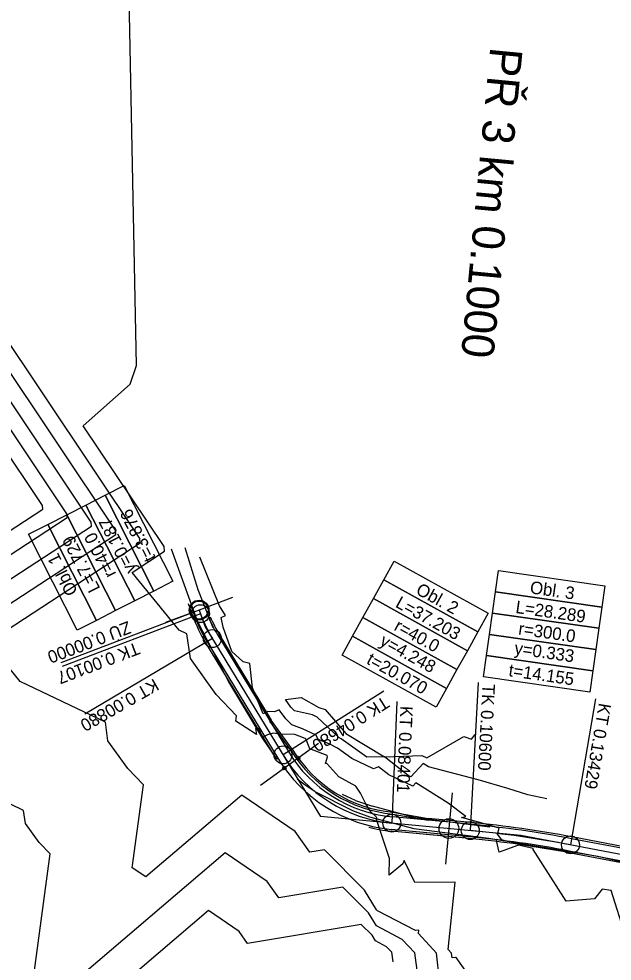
# Model space of a CAD drawing. Extents: x -549394 to -546608, y -1037055 to -1033629.
# Drawn here: x -547175.8 to -547010.1, y -1035814.9 to -1035551.8 of the extents above; entities that cross this region are included whole.
import ezdxf

# ---------------------------------------------------------------- set-up
doc = ezdxf.new("R2010")
doc.units = 0
for name, color, linetype in [('hlavni_vrst', 7, 'Continuous'), ('hrana_L', 7, 'Continuous'), ('norm_vrst', 7, 'Continuous'), ('POLYGONY_SITUACE_PO', 7, 'Continuous'), ('u_sirka_0_5m', 7, 'Continuous'), ('x_navrh_C3', 7, 'Continuous'), ('x_osa_C3', 7, 'Continuous'), ('x_popis_oblouky_C3', 7, 'Continuous'), ('x_popis_pricne_rezy_C3', 7, 'Continuous')]:
    doc.layers.add(name, color=color, linetype=linetype)

msp = doc.modelspace()

# ---------------------------------------------------------------- linework, layer by layer
at = {"layer": 'hlavni_vrst'}
for p, q in [((-547162.43, -1035690), (-547254.53, -1035552.4)), ((-547270.81, -1035761.75), (-547162.32, -1035691.07)), ((-547162.32, -1035691.07), (-547162.43, -1035690)), ((-547119.76, -1035715.7), (-547125.23, -1035702.15)), ((-547118.11, -1035718.38), (-547119.76, -1035715.7)), ((-547119.32, -1035718.91), (-547118.11, -1035718.38)), ((-547118.72, -1035721.68), (-547119.32, -1035718.91)), ((-547116.35, -1035728.46), (-547118.72, -1035721.68)), ((-547113.14, -1035731.35), (-547116.35, -1035728.46)), ((-547111.32, -1035731.79), (-547113.14, -1035731.35)), ((-547110.54, -1035738.54), (-547111.32, -1035731.79)), ((-547107.57, -1035745.83), (-547110.54, -1035738.54)), ((-547106.28, -1035745.18), (-547107.57, -1035745.83)), ((-547104.38, -1035745.28), (-547106.28, -1035745.18)), ((-547103.1, -1035744.71), (-547104.38, -1035745.28)), ((-547101.24, -1035747.24), (-547103.1, -1035744.71)), ((-547099.56, -1035748.9), (-547101.24, -1035747.24)), ((-547096.55, -1035750.05), (-547099.56, -1035748.9)), ((-547092.78, -1035751.76), (-547096.55, -1035750.05)), ((-547092.25, -1035752.99), (-547092.78, -1035751.76)), ((-547089.09, -1035754.2), (-547092.25, -1035752.99)), ((-547086.83, -1035755.45), (-547089.09, -1035754.2)), ((-547082.83, -1035758.29), (-547086.83, -1035755.45)), ((-547076.73, -1035761.22), (-547082.83, -1035758.29)), ((-547075.38, -1035760.61), (-547076.73, -1035761.22)), ((-547072.5, -1035762.9), (-547075.38, -1035760.61)), ((-547065.74, -1035766.01), (-547072.5, -1035762.9)), ((-547064.9, -1035765.1), (-547065.74, -1035766.01)), ((-547055.9, -1035770.76), (-547064.9, -1035765.1)), ((-547050.97, -1035774.54), (-547055.9, -1035770.76)), ((-547052.14, -1035774.74), (-547050.97, -1035774.54)), ((-547044.71, -1035776.82), (-547052.14, -1035774.74)), ((-547041.66, -1035777.75), (-547044.71, -1035776.82)), ((-547042.1, -1035779.39), (-547041.66, -1035777.75)), ((-547041.65, -1035784.48), (-547042.49, -1035780.85)), ((-547042.49, -1035780.85), (-547039.99, -1035781.26)), ((-547040.91, -1035781.03), (-547042.1, -1035779.39)), ((-547039.99, -1035781.26), (-547040.91, -1035781.03)), ((-547036.28, -1035782.48), (-547041.65, -1035784.48)), ((-547032.12, -1035783.41), (-547036.28, -1035782.48)), ((-547032.16, -1035783.69), (-547032.12, -1035783.41)), ((-547022.93, -1035798.11), (-547032.16, -1035783.69)), ((-547012.88, -1035794.76), (-547015.05, -1035797.51)), ((-547010.39, -1035795.15), (-547012.88, -1035794.76)), ((-547006.35, -1035807.78), (-547010.39, -1035795.15)), ((-547015.05, -1035797.51), (-547022.93, -1035798.11))]:
    msp.add_line(p, q, dxfattribs=at)
at = {"layer": 'hrana_L'}
for p, q in [((-547133.31, -1035699.8), (-547126.03, -1035719.9)), ((-547125.75, -1035711.25), (-547129.4, -1035699.51)), ((-547121.54, -1035721.79), (-547125.75, -1035711.25)), ((-547126.03, -1035719.9), (-547116.97, -1035737.34)), ((-547116.97, -1035737.34), (-547107.79, -1035752.71)), ((-547107.79, -1035752.71), (-547104.47, -1035757.48)), ((-547104.47, -1035757.48), (-547103.62, -1035758.54)), ((-547095.87, -1035765.77), (-547098.09, -1035764.1)), ((-547093.16, -1035767.56), (-547095.87, -1035765.77)), ((-547093.16, -1035767.56), (-547082.65, -1035772.78)), ((-547081.81, -1035770.01), (-547085.39, -1035768.38)), ((-547081.81, -1035770.01), (-547076.99, -1035771.58)), ((-547082.65, -1035772.78), (-547077.83, -1035774.58)), ((-547065.04, -1035774.86), (-547076.99, -1035771.58)), ((-547077.83, -1035774.58), (-547065.49, -1035777.83)), ((-547044.23, -1035777.49), (-547065.04, -1035774.86)), ((-547065.49, -1035777.83), (-547044.51, -1035780.5)), ((-547044.51, -1035780.5), (-547014.03, -1035785.6)), ((-547014.03, -1035785.6), (-546993.98, -1035790.12))]:
    msp.add_line(p, q, dxfattribs=at)
at = {"layer": 'norm_vrst'}
for p, q in [((-547142.94, -1035648.57), (-547145.95, -1035499.25)), ((-547148.85, -1035694.57), (-547251.98, -1035540.5)), ((-547155.64, -1035692.29), (-547253.25, -1035546.45)), ((-547142.07, -1035696.85), (-547242.38, -1035546.99)), ((-547169.21, -1035687.72), (-547255.8, -1035558.35)), ((-547144.77, -1035653.79), (-547142.94, -1035648.57)), ((-547157.83, -1035665.45), (-547144.77, -1035653.79)), ((-547135.28, -1035699.14), (-547157.83, -1035665.45)), ((-547271.11, -1035755.18), (-547169.11, -1035688.72)), ((-547169.11, -1035688.72), (-547169.21, -1035687.72)), ((-547264.92, -1035764.69), (-547155.53, -1035693.41)), ((-547155.53, -1035693.41), (-547155.64, -1035692.29)), ((-547148.73, -1035695.76), (-547148.85, -1035694.57)), ((-547224.67, -1035745.24), (-547148.73, -1035695.76)), ((-547141.94, -1035698.11), (-547142.07, -1035696.85)), ((-547184.42, -1035725.79), (-547141.94, -1035698.11)), ((-547135.14, -1035700.46), (-547135.28, -1035699.14)), ((-547144.18, -1035706.34), (-547135.14, -1035700.46)), ((-547131.02, -1035722.49), (-547144.18, -1035706.34)), ((-547128.86, -1035723.52), (-547131.02, -1035722.49)), ((-547127.92, -1035730.37), (-547128.86, -1035723.52)), ((-547175.46, -1035736.8), (-547184.42, -1035725.79)), ((-547120.68, -1035740.44), (-547127.92, -1035730.37)), ((-547151.67, -1035748.16), (-547175.46, -1035736.8)), ((-547114.98, -1035746.4), (-547120.68, -1035740.44)), ((-547101.36, -1035741.88), (-547096.97, -1035741.25)), ((-547099.84, -1035743.95), (-547101.36, -1035741.88)), ((-547096.97, -1035741.25), (-547092.03, -1035744.04)), ((-547098.79, -1035744.99), (-547099.84, -1035743.95)), ((-547092.03, -1035744.04), (-547090.21, -1035744.59)), ((-547090.21, -1035744.59), (-547084.45, -1035751.36)), ((-547115.18, -1035747.91), (-547114.98, -1035746.4)), ((-547093.75, -1035746.09), (-547098.79, -1035744.99)), ((-547092.47, -1035746.77), (-547093.75, -1035746.09)), ((-547086.48, -1035752.45), (-547092.47, -1035746.77)), ((-547150.95, -1035753.4), (-547151.67, -1035748.16)), ((-547109.47, -1035751.65), (-547115.18, -1035747.91)), ((-547109.72, -1035749.47), (-547109.33, -1035750.16)), ((-547108.72, -1035750.14), (-547109.72, -1035749.47)), ((-547174.49, -1035772.8), (-547219.89, -1035751.1)), ((-547109.33, -1035750.16), (-547109.74, -1035749.92)), ((-547109.74, -1035749.92), (-547109.47, -1035751.65)), ((-547107.78, -1035752.45), (-547108.72, -1035750.14)), ((-547106.32, -1035751.7), (-547107.78, -1035752.45)), ((-547104.82, -1035751.21), (-547106.32, -1035751.7)), ((-547102.85, -1035751.5), (-547104.82, -1035751.21)), ((-547098.7, -1035751.63), (-547102.85, -1035751.5)), ((-547096.32, -1035752.55), (-547098.7, -1035751.63)), ((-547085.76, -1035752.84), (-547086.48, -1035752.45)), ((-547084.45, -1035751.36), (-547073.72, -1035757.81)), ((-547061.85, -1035758.15), (-547051.54, -1035752.15)), ((-547051.54, -1035752.15), (-547049.41, -1035752.95)), ((-547049.41, -1035752.95), (-547048.34, -1035751.56)), ((-547145.41, -1035761.11), (-547150.95, -1035753.4)), ((-547095.69, -1035752.83), (-547096.32, -1035752.55)), ((-547094.49, -1035755.63), (-547095.69, -1035752.83)), ((-547078.6, -1035757.93), (-547085.76, -1035752.84)), ((-547089.7, -1035757.46), (-547094.49, -1035755.63)), ((-547089.6, -1035757.81), (-547089.7, -1035757.46)), ((-547073.72, -1035757.81), (-547063.29, -1035757.51)), ((-547063.29, -1035757.51), (-547061.85, -1035758.15)), ((-547090.19, -1035759.74), (-547089.6, -1035757.81)), ((-547089.83, -1035759.74), (-547090.19, -1035759.74)), ((-547086.44, -1035763.39), (-547089.83, -1035759.74)), ((-547073.72, -1035757.81), (-547078.6, -1035757.93)), ((-547073.72, -1035757.81), (-547073.72, -1035757.81)), ((-547073.72, -1035757.81), (-547073.72, -1035757.81)), ((-547073.72, -1035757.81), (-547073.72, -1035757.81)), ((-547067.1, -1035763.08), (-547073.72, -1035757.81)), ((-547062.85, -1035759.69), (-547066.32, -1035763.43)), ((-547061.39, -1035760.61), (-547062.85, -1035759.69)), ((-547141.05, -1035765.67), (-547145.41, -1035761.11)), ((-547047.55, -1035764.26), (-547061.39, -1035760.61)), ((-547144.14, -1035788.82), (-547141.05, -1035765.67)), ((-547081.68, -1035765.99), (-547086.44, -1035763.39)), ((-547066.32, -1035763.43), (-547067.1, -1035763.08)), ((-547039.2, -1035766.69), (-547047.55, -1035764.26)), ((-547080.36, -1035767.97), (-547081.68, -1035765.99)), ((-547078.92, -1035770.95), (-547080.36, -1035767.97)), ((-547033.59, -1035768.43), (-547039.2, -1035766.69)), ((-547113.56, -1035768.54), (-547140.31, -1035791.32)), ((-547098.64, -1035778.68), (-547113.56, -1035768.54)), ((-547078.3, -1035771.86), (-547078.92, -1035770.95)), ((-547028.36, -1035769.53), (-547033.59, -1035768.43)), ((-547173.98, -1035776.43), (-547174.49, -1035772.8)), ((-547077.45, -1035773.22), (-547078.3, -1035771.86)), ((-547076, -1035774.62), (-547077.45, -1035773.22)), ((-547076.04, -1035775.07), (-547075.7, -1035775.14)), ((-547072.24, -1035786.23), (-547076.04, -1035775.07)), ((-547075.7, -1035775.14), (-547076, -1035774.62)), ((-547170.14, -1035781.78), (-547173.98, -1035776.43)), ((-547094.5, -1035784.45), (-547098.64, -1035778.68)), ((-547167.12, -1035784.94), (-547170.14, -1035781.78)), ((-547090.47, -1035783.78), (-547094.5, -1035784.45)), ((-547079.24, -1035795.04), (-547090.47, -1035783.78)), ((-547173.1, -1035829.73), (-547167.12, -1035784.94)), ((-547118.23, -1035784.65), (-547172, -1035830.44)), ((-547106.48, -1035792.64), (-547118.23, -1035784.65)), ((-547072.34, -1035790.87), (-547072.24, -1035786.23)), ((-547140.31, -1035791.32), (-547144.14, -1035788.82)), ((-547068.52, -1035787.69), (-547072.34, -1035790.87)), ((-547068.17, -1035786.78), (-547068.52, -1035787.69)), ((-547065.22, -1035792.95), (-547068.17, -1035786.78)), ((-547103.21, -1035797.19), (-547106.48, -1035792.64)), ((-547085.31, -1035794.19), (-547103.21, -1035797.19)), ((-547078.18, -1035801.34), (-547085.31, -1035794.19)), ((-547053.89, -1035792.84), (-547065.22, -1035792.95)), ((-547055.88, -1035811.62), (-547053.89, -1035792.84)), ((-547075.91, -1035800.52), (-547079.24, -1035795.04)), ((-547122.89, -1035800.77), (-547175.77, -1035845.79)), ((-547114.31, -1035806.6), (-547122.89, -1035800.77)), ((-547075.93, -1035805.04), (-547078.18, -1035801.34)), ((-547075.67, -1035800.82), (-547075.91, -1035800.52)), ((-547075.64, -1035800.85), (-547075.67, -1035800.82)), ((-547065, -1035806.27), (-547075.64, -1035800.85)), ((-547080.15, -1035804.6), (-547111.93, -1035809.92)), ((-547077.12, -1035807.65), (-547080.15, -1035804.6)), ((-547068.74, -1035808.83), (-547075.93, -1035805.04)), ((-547111.93, -1035809.92), (-547114.31, -1035806.6)), ((-547076.16, -1035809.22), (-547077.12, -1035807.65)), ((-547064.08, -1035806.26), (-547065, -1035806.27)), ((-547064.18, -1035807.15), (-547064.08, -1035806.26)), ((-547059.16, -1035812.61), (-547064.18, -1035807.15)), ((-547073.1, -1035810.83), (-547076.16, -1035809.22)), ((-547065.22, -1035812.51), (-547068.74, -1035808.83)), ((-547071.6, -1035812.4), (-547073.1, -1035810.83)), ((-547071.22, -1035815.06), (-547071.6, -1035812.4)), ((-547064.32, -1035818.79), (-547065.22, -1035812.51)), ((-547058.28, -1035820.05), (-547059.16, -1035812.61)), ((-547054.97, -1035812.6), (-547055.88, -1035811.62)), ((-547054.81, -1035813.94), (-547054.97, -1035812.6)), ((-547053.86, -1035813.86), (-547054.81, -1035813.94)), ((-547053.67, -1035813.88), (-547053.86, -1035813.86)), ((-547049.05, -1035820.28), (-547053.67, -1035813.88))]:
    msp.add_line(p, q, dxfattribs=at)
at = {"layer": 'POLYGONY_SITUACE_PO'}
for centre in [(-547125.48, -1035716.87), (-547125.11, -1035717.88), (-547121.76, -1035724.83), (-547102.02, -1035757.3), (-547071.61, -1035776.34), (-547049.71, -1035778.42), (-547021.72, -1035782.42)]:
    msp.add_circle(centre, 2.5, dxfattribs=at)
at = {"layer": 'u_sirka_0_5m'}
for centre, radius in [((-547125.48, -1035716.87), 2.75), ((-547097.79, -1035758.18), 0.5), ((-547101.67, -1035760.99), 0.5), ((-547055.69, -1035777.85), 2.75)]:
    msp.add_circle(centre, radius, dxfattribs=at)
at = {"layer": 'x_navrh_C3'}
for p, q in [((-547127.87, -1035715.43), (-547126.75, -1035718.48)), ((-547123.25, -1035725.73), (-547103.51, -1035758.21)), ((-547120.26, -1035723.92), (-547100.52, -1035756.39)), ((-547099.85, -1035755.98), (-547105.72, -1035747.85)), ((-547099.43, -1035755.7), (-547105.3, -1035747.57)), ((-547071.31, -1035773.32), (-547061.43, -1035775.05)), ((-547049.55, -1035776.68), (-547071.45, -1035774.6)), ((-547071.37, -1035773.82), (-547061.49, -1035775.55)), ((-547049.93, -1035780.66), (-547071.83, -1035778.58)), ((-547049.88, -1035780.16), (-547071.78, -1035778.09)), ((-546982.7, -1035788.09), (-547021.39, -1035780.7)), ((-546983.36, -1035791.53), (-547022.05, -1035784.13))]:
    msp.add_line(p, q, dxfattribs=at)
for points in [[(-547128.56, -1035715.02), (-547127.22, -1035718.65)], [(-547123.68, -1035725.99), (-547103.94, -1035758.47)], [(-547119.83, -1035723.66), (-547105.3, -1035747.57)], [(-547049.5, -1035776.18), (-547061.43, -1035775.05)], [(-547049.93, -1035780.66), (-547062.08, -1035779.51)], [(-546982.61, -1035787.6), (-547021.3, -1035780.21)], [(-546983.45, -1035792.02), (-547022.14, -1035784.63)]]:
    msp.add_lwpolyline(points, dxfattribs=at)
for centre, radius, start, end in [((-547087.57, -1035704.05), 38.25, 201.9092, 211.2924), ((-547087.57, -1035704.05), 42.25, 200.2219, 211.2924), ((-547087.57, -1035704.05), 41.75, 200.2219, 211.2924), ((-547087.57, -1035704.05), 37.75, 202.9245, 211.2924), ((-547067.84, -1035736.52), 38.25, 211.2924, 264.5817), ((-547067.84, -1035736.52), 37.46, 211.2924, 264.5817), ((-547067.84, -1035736.52), 36.96, 211.262, 264.6122), ((-547067.84, -1035736.52), 41.75, 211.2924, 264.5817), ((-547078.04, -1036077.08), 302.25, 79.1789, 84.5817), ((-547067.84, -1035736.52), 42.25, 255.9517, 264.5817), ((-547078.04, -1036077.08), 301.75, 79.1789, 84.5817), ((-547078.04, -1036077.08), 297.75, 79.1789, 84.5817), ((-547078.04, -1036077.08), 298.25, 79.1789, 84.5817)]:
    msp.add_arc(centre, radius, start, end, dxfattribs=at)
at = {"layer": 'x_osa_C3'}
for points in [[(-547125.48, -1035716.87), (-547123.77, -1035721.51), (-547091.59, -1035774.45)], [(-546884.98, -1035809.13), (-546939.06, -1035799.39), (-546975.39, -1035791.27), (-547035.62, -1035779.76), (-547091.59, -1035774.45)]]:
    msp.add_lwpolyline(points, dxfattribs=at)
for centre, radius, start, end in [((-547087.57, -1035704.05), 40, 200.2219, 211.2924), ((-547067.84, -1035736.52), 40, 211.2924, 264.5817), ((-547078.04, -1036077.08), 300, 79.1789, 84.5817)]:
    msp.add_arc(centre, radius, start, end, dxfattribs=at)
at = {"layer": 'x_popis_oblouky_C3'}
for points in [[(-547138.12, -1035711.57), (-547151.74, -1035684.84), (-547146.39, -1035682.11), (-547132.77, -1035708.84)], [(-547143.46, -1035714.29), (-547157.08, -1035687.56), (-547151.74, -1035684.84), (-547138.12, -1035711.57)], [(-547148.81, -1035717.01), (-547162.43, -1035690.28), (-547157.08, -1035687.56), (-547143.46, -1035714.29)], [(-547154.16, -1035719.74), (-547167.77, -1035693.01), (-547162.43, -1035690.28), (-547148.81, -1035717.01)], [(-547159.5, -1035722.46), (-547173.12, -1035695.73), (-547167.77, -1035693.01), (-547154.16, -1035719.74)], [(-547070.97, -1035703.19), (-547044.72, -1035717.72), (-547047.63, -1035722.97), (-547073.87, -1035708.44)], [(-547041.79, -1035705.84), (-547012.09, -1035710.09), (-547012.94, -1035716.03), (-547042.64, -1035711.78)], [(-547073.87, -1035708.44), (-547047.63, -1035722.97), (-547050.53, -1035728.22), (-547076.78, -1035713.69)], [(-547042.64, -1035711.78), (-547012.94, -1035716.03), (-547013.79, -1035721.97), (-547043.49, -1035717.72)], [(-547076.78, -1035713.69), (-547050.53, -1035728.22), (-547053.44, -1035733.47), (-547079.69, -1035718.94)], [(-547043.49, -1035717.72), (-547013.79, -1035721.97), (-547014.64, -1035727.9), (-547044.33, -1035723.66)], [(-547079.69, -1035718.94), (-547053.44, -1035733.47), (-547056.34, -1035738.72), (-547082.59, -1035724.19)], [(-547082.59, -1035724.19), (-547056.34, -1035738.72), (-547059.25, -1035743.97), (-547085.5, -1035729.44)], [(-547044.33, -1035723.66), (-547014.64, -1035727.9), (-547015.48, -1035733.84), (-547045.18, -1035729.6)], [(-547045.18, -1035729.6), (-547015.48, -1035733.84), (-547016.33, -1035739.78), (-547046.03, -1035735.54)]]:
    msp.add_lwpolyline(points, close=True, dxfattribs=at)
for points in [[(-547125.48, -1035716.87), (-547164.13, -1035731.63)], [(-547125.11, -1035717.88), (-547163.76, -1035732.63)], [(-547121.76, -1035724.83), (-547157.36, -1035745.9)], [(-547047.52, -1035737.11), (-547049.71, -1035778.42)], [(-547073.9, -1035739.54), (-547102.02, -1035757.3)], [(-547014.71, -1035741.64), (-547021.72, -1035782.42)], [(-547070.22, -1035742.38), (-547071.61, -1035776.34)]]:
    msp.add_lwpolyline(points, dxfattribs=at)
at = {"layer": 'x_popis_pricne_rezy_C3'}
for points in [[(-547116.1, -1035713.41), (-547125.48, -1035716.87), (-547134.86, -1035720.33)], [(-547092.15, -1035754.1), (-547100.25, -1035759.96), (-547108.35, -1035765.82)], [(-547054.75, -1035767.9), (-547055.69, -1035777.85), (-547056.63, -1035787.81)]]:
    msp.add_lwpolyline(points, dxfattribs=at)

# ---------------------------------------------------------------- texts
at = {"layer": 'x_popis_oblouky_C3'}
for s, rotation, p in [('t=3.876', 117.0177, (-547137.46, -1035702.3)), ('y=0.187', 117.0177, (-547142.9, -1035705.6)), ('L=7.729', 117.0177, (-547153, -1035710.87)), ('r=40.0', 117.0177, (-547148.55, -1035706.77)), ('Obl. 1', 117.0177, (-547159.27, -1035711.78)), ('Obl. 2', 331.0542, (-547065.18, -1035712.17)), ('Obl. 3', 351.8918, (-547033.19, -1035712.18)), ('L=37.203', 331.0542, (-547070.89, -1035715.87)), ('L=28.289', 351.8918, (-547037.21, -1035717.67)), ('ZÚ 0.00000', 200.8942, (-547145.32, -1035719.88)), ('r=40.0', 331.0542, (-547071.27, -1035722.33)), ('r=300.0', 351.8918, (-547036.42, -1035723.67)), ('TK 0.00107', 200.8942, (-547142.93, -1035725.74)), ('y=4.248', 331.0542, (-547075.29, -1035726.45)), ('y=0.333', 351.8918, (-547037.55, -1035729.12)), ('t=20.070', 331.0542, (-547078.97, -1035731.67)), ('t=14.155', 351.8918, (-547039.14, -1035735.31)), ('KT 0.00880', 209.8408, (-547138.05, -1035735.87)), ('TK 0.10600', 266.9549, (-547046.28, -1035737.43)), ('TK 0.04680', 212.2757, (-547073.85, -1035740.77)), ('KT 0.08401', 267.6461, (-547069.24, -1035743.59)), ('KT 0.13429', 260.2469, (-547013.76, -1035742.66))]:
    msp.add_text(s, height=3.5, rotation=rotation, dxfattribs=at).set_placement(p)
at = {"layer": 'x_popis_pricne_rezy_C3'}
msp.add_text('PŘ 3 km 0.1000', height=9.0627, rotation=264.5817, dxfattribs=at).set_placement((-547044.09, -1035559.53))

doc.saveas('drawing.dxf')
